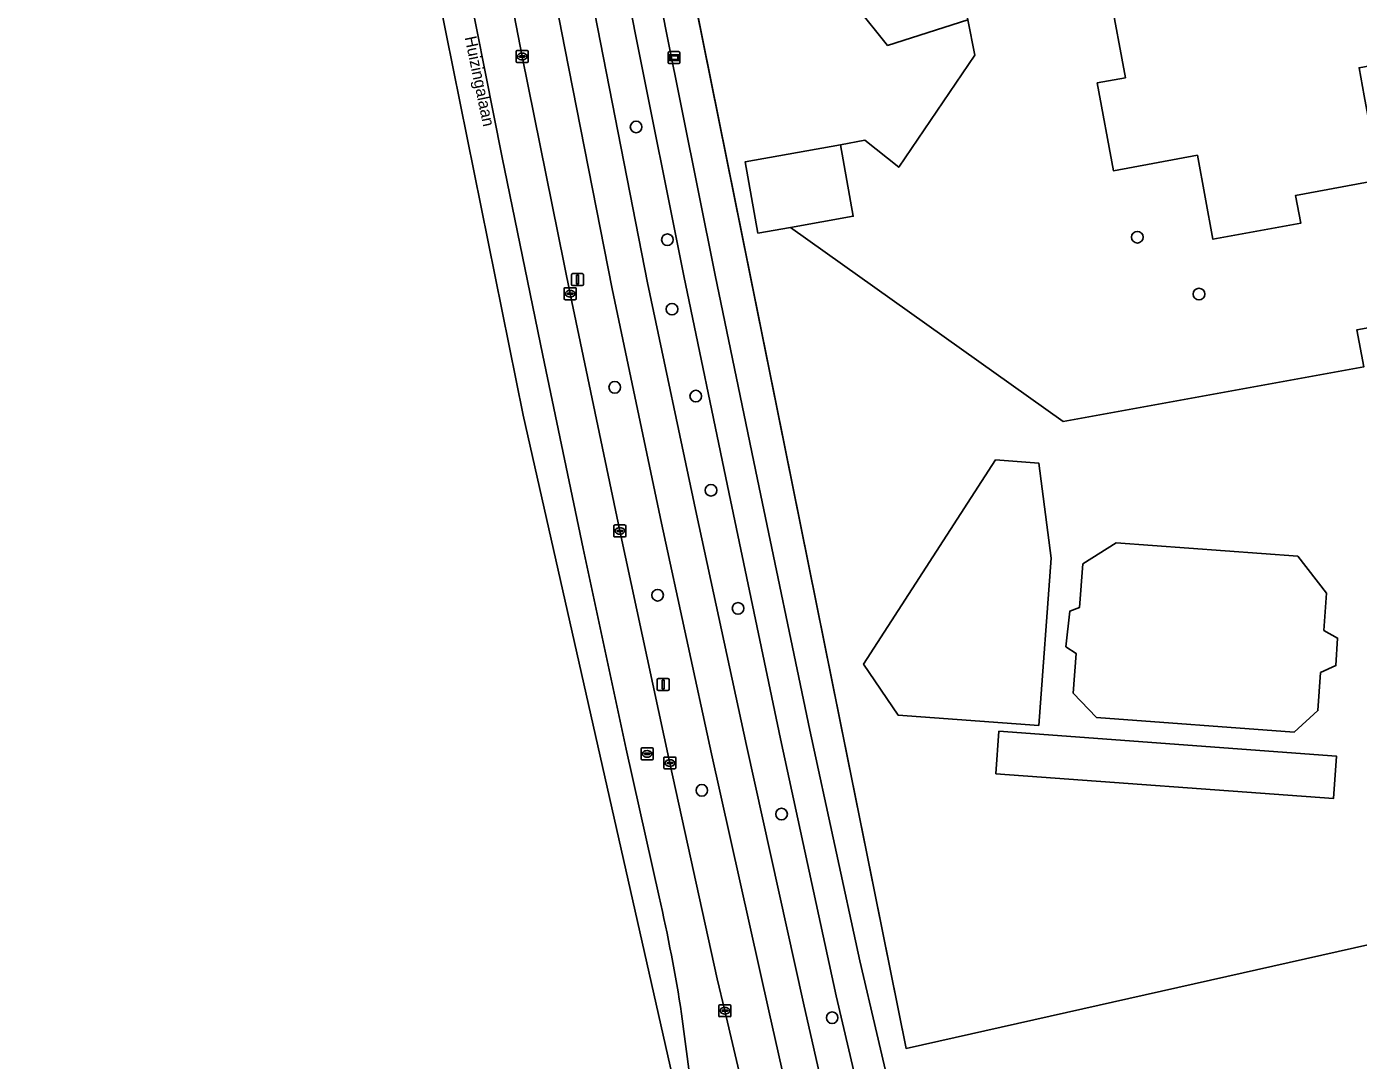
# Model space of a CAD drawing. Extents: x 159451 to 160664, y 388402 to 389723.
# Drawn here: x 159488.5 to 159600.6, y 388755.7 to 388842.8 of the extents above; entities that cross this region are included whole.
import ezdxf

# ---------------------------------------------------------------- set-up
doc = ezdxf.new("R2010")
doc.units = 0
for name, color, linetype in [('IMGEO_Berm_groen', 7, 'Continuous'), ('IMGEO_Boom', 7, 'Continuous'), ('IMGEO_Erf', 7, 'Continuous'), ('IMGEO_Fietspad_gesloten', 7, 'Continuous'), ('IMGEO_Groenvoorziening', 7, 'Continuous'), ('IMGEO_Hek', 7, 'Continuous'), ('IMGEO_Kolk', 7, 'Continuous'), ('IMGEO_Lichtmast', 7, 'Continuous'), ('IMGEO_Loofbos', 7, 'Continuous'), ('IMGEO_Openbare_ruimte_label', 7, 'Continuous'), ('IMGEO_OVBaan_gesloten', 7, 'Continuous'), ('IMGEO_Pand', 7, 'Continuous'), ('IMGEO_Rijbaan_regionaal_gesloten', 7, 'Continuous'), ('IMGEO_Rioolput', 7, 'Continuous'), ('IMGEO_Terreindeel_zand', 7, 'Continuous'), ('IMGEO_Verklikker', 7, 'Continuous'), ('IMGEO_Voetpad_open', 7, 'Continuous')]:
    doc.layers.add(name, color=color, linetype=linetype)

msp = doc.modelspace()

# ---------------------------------------------------------------- linework, layer by layer
at = {"layer": 'IMGEO_Berm_groen'}
for points in [[(159507.46, 388965.11), (159508.35, 388959.87), (159508.7, 388957.75), (159512.08, 388938.65), (159515.61, 388918.53), (159519.19, 388898.44), (159522.9, 388878.37), (159526.53, 388859.3), (159530.22, 388840.26), (159534.26, 388820.29), (159538.44, 388800.32), (159542.65, 388780.78), (159546.64, 388762.61), (159547.28, 388759.93), (159551.72, 388741.02), (159556.37, 388721.14), (159560.62, 388703.15), (159561.07, 388701.2), (159561.59, 388698.98)], [(159564.81, 388699.67), (159563.77, 388704.28), (159559.07, 388724.6), (159555.06, 388741.81), (159550.97, 388759.91), (159546.15, 388781.55), (159541.95, 388800.98), (159537.8, 388820.69), (159533.81, 388840.97), (159530.09, 388859.95), (159526.35, 388879.41), (159522.62, 388899.25), (159519.02, 388919.06), (159516.59, 388932.87), (159512.11, 388958.35), (159511.9, 388959.73), (159511.08, 388964.83)], [(159533.29, 388859.39), (159536.81, 388841.45), (159540.76, 388821.22), (159544.88, 388801.72), (159549.09, 388782.26), (159553.91, 388760.57), (159558.53, 388740.16), (159562.68, 388722.31), (159566.81, 388704.48), (159567.82, 388699.99), (159570.89, 388700.66), (159570.66, 388701.6), (159569.8, 388705.34), (159560.7, 388743.94), (159556.66, 388761.18), (159551.96, 388782.81), (159547.49, 388804.12), (159543.82, 388821.79), (159539.76, 388842.11), (159535.83, 388862.33)]]:
    msp.add_lwpolyline(points, dxfattribs=at)
at = {"layer": 'IMGEO_Boom'}
for centre in [(159539.81, 388834.33), (159542.44, 388824.84), (159582, 388825.05), (159587.19, 388820.26), (159542.83, 388818.99), (159538.01, 388812.41), (159544.83, 388811.67), (159546.11, 388803.74), (159541.62, 388794.91), (159548.39, 388793.8), (159545.34, 388778.48), (159552.05, 388776.48), (159556.31, 388759.34)]:
    msp.add_circle(centre, 0.489, dxfattribs=at)
at = {"layer": 'IMGEO_Erf'}
for points in [[(159538.55, 388875.67), (159562.53, 388756.76), (159678.25, 388782.74), (159689.42, 388833.24), (159688.56, 388837.48), (159685.61, 388852.04)], [(159662.98, 388848.82), (159665.86, 388835.05), (159663.92, 388832.1), (159657.18, 388821.94), (159652.89, 388824.78), (159637.51, 388830.55), (159632.91, 388823.15), (159600.49, 388817.26), (159601.06, 388814.13), (159575.75, 388809.53), (159552.81, 388825.88), (159550.06, 388825.39), (159548.99, 388831.4), (159557.02, 388832.83), (159559.07, 388833.23), (159561.91, 388830.94), (159568.33, 388840.38), (159567.72, 388843.34), (159560.98, 388841.19), (159555.74, 388847.74)]]:
    msp.add_lwpolyline(points, dxfattribs=at)
for points in [[(159574.74, 388798.04), (159573.7, 388783.95), (159561.86, 388784.82), (159558.95, 388789.11), (159570.07, 388806.3), (159573.7, 388806.03)], [(159597.7, 388791.94), (159597.93, 388795.08), (159595.51, 388798.19), (159580.22, 388799.32), (159577.4, 388797.55), (159577.13, 388793.87), (159576.32, 388793.57), (159575.99, 388790.57), (159576.84, 388790.01), (159576.6, 388786.67), (159578.57, 388784.61), (159595.21, 388783.38), (159597.2, 388785.2), (159597.43, 388788.39), (159598.71, 388788.98), (159598.86, 388791.3)], [(159597.7, 388791.94), (159598.86, 388791.3), (159598.71, 388788.98), (159597.43, 388788.39), (159597.2, 388785.2), (159595.21, 388783.38), (159578.57, 388784.61), (159576.6, 388786.67), (159576.84, 388790.01), (159575.99, 388790.57), (159576.32, 388793.57), (159577.13, 388793.87), (159577.4, 388797.55), (159580.22, 388799.32), (159595.51, 388798.19), (159597.93, 388795.08)], [(159570.35, 388783.45), (159570.09, 388779.88), (159598.51, 388777.78), (159598.77, 388781.35)], [(159598.77, 388781.35), (159598.51, 388777.78), (159570.09, 388779.88), (159570.35, 388783.45)]]:
    msp.add_lwpolyline(points, close=True, dxfattribs=at)
at = {"layer": 'IMGEO_Fietspad_gesloten'}
for points in [[(159540.76, 388821.22), (159536.81, 388841.45), (159533.29, 388859.39), (159529.26, 388880.34), (159525.53, 388900.16), (159521.97, 388919.7), (159518.43, 388939.84), (159516.78, 388949.35), (159515.14, 388958.74), (159514.42, 388963.29)], [(159530.09, 388859.95), (159533.81, 388840.97), (159537.8, 388820.69), (159541.95, 388800.98), (159546.15, 388781.55), (159550.97, 388759.91), (159555.06, 388741.81), (159559.07, 388724.6), (159563.77, 388704.28), (159564.81, 388699.67), (159567.82, 388699.99), (159566.81, 388704.48), (159562.68, 388722.31), (159558.53, 388740.16), (159553.91, 388760.57), (159549.09, 388782.26), (159544.88, 388801.72), (159540.76, 388821.22)]]:
    msp.add_lwpolyline(points, dxfattribs=at)
at = {"layer": 'IMGEO_Groenvoorziening'}
msp.add_lwpolyline([(159574.74, 388798.04), (159573.7, 388806.03), (159570.07, 388806.3), (159558.95, 388789.11), (159561.86, 388784.82), (159573.7, 388783.95)], close=True, dxfattribs=at)
at = {"layer": 'IMGEO_Hek'}
msp.add_lwpolyline([(159678.25, 388782.74), (159562.53, 388756.76), (159538.54, 388875.75), (159538.12, 388877.8), (159532.82, 388904.1), (159527.33, 388934.89), (159516.65, 389000), (159504.91, 389075.55), (159505.31, 389078.14), (159506.99, 389079.73), (159534.92, 389087.14), (159543.41, 389088.84), (159556.65, 389090.59), (159574.7, 389093.29)], dxfattribs=at)
at = {"layer": 'IMGEO_Kolk'}
for p, q in [((159529.72, 388839.84), (159529.72, 388840.69)), ((159529.79, 388840.76), (159530.64, 388840.76)), ((159530.72, 388840.69), (159530.72, 388839.84)), ((159530.64, 388839.76), (159529.79, 388839.76)), ((159529.98, 388840.26), (159529.98, 388840.27)), ((159530.02, 388840.31), (159530.42, 388840.31)), ((159530.41, 388840.22), (159530.02, 388840.22)), ((159530.23, 388839.98), (159530.2, 388839.98)), ((159530.21, 388840.54), (159530.23, 388840.54)), ((159530.46, 388840.27), (159530.46, 388840.26)), ((159533.76, 388819.87), (159533.76, 388820.72)), ((159533.83, 388820.79), (159534.69, 388820.79)), ((159534.25, 388820.57), (159534.27, 388820.57)), ((159534.76, 388820.72), (159534.76, 388819.87)), ((159534.69, 388819.79), (159533.83, 388819.79)), ((159534.02, 388820.29), (159534.02, 388820.3)), ((159534.06, 388820.34), (159534.46, 388820.34)), ((159534.45, 388820.25), (159534.06, 388820.25)), ((159534.27, 388820.01), (159534.24, 388820.01)), ((159534.5, 388820.3), (159534.5, 388820.29)), ((159537.94, 388799.89), (159537.94, 388800.75)), ((159538.01, 388800.82), (159538.87, 388800.82)), ((159538.2, 388800.31), (159538.2, 388800.33)), ((159538.24, 388800.36), (159538.64, 388800.36)), ((159538.43, 388800.6), (159538.45, 388800.6)), ((159538.68, 388800.33), (159538.68, 388800.31)), ((159538.94, 388800.75), (159538.94, 388799.89)), ((159538.87, 388799.82), (159538.01, 388799.82)), ((159538.64, 388800.28), (159538.24, 388800.28)), ((159538.45, 388800.04), (159538.42, 388800.04)), ((159542.23, 388781.28), (159543.08, 388781.28)), ((159542.15, 388780.35), (159542.15, 388781.21)), ((159543.08, 388780.28), (159542.23, 388780.28)), ((159542.41, 388780.77), (159542.41, 388780.79)), ((159542.85, 388780.74), (159542.45, 388780.74)), ((159542.46, 388780.82), (159542.85, 388780.82)), ((159542.64, 388781.06), (159542.67, 388781.06)), ((159542.66, 388780.5), (159542.64, 388780.5)), ((159542.9, 388780.79), (159542.9, 388780.77)), ((159543.16, 388781.21), (159543.16, 388780.35)), ((159546.78, 388759.5), (159546.78, 388760.35)), ((159546.85, 388760.43), (159547.71, 388760.43)), ((159547.08, 388759.97), (159547.48, 388759.97)), ((159547.27, 388760.21), (159547.29, 388760.21)), ((159547.78, 388760.35), (159547.78, 388759.5)), ((159547.71, 388759.43), (159546.85, 388759.43)), ((159547.04, 388759.92), (159547.04, 388759.93)), ((159547.47, 388759.88), (159547.08, 388759.88)), ((159547.29, 388759.65), (159547.26, 388759.65)), ((159547.52, 388759.93), (159547.52, 388759.92))]:
    msp.add_line(p, q, dxfattribs=at)
for points in [[(159529.72, 388839.84), (159529.72, 388840.69)], [(159529.79, 388840.76), (159530.64, 388840.76)], [(159530.72, 388840.69), (159530.72, 388839.84)], [(159530.64, 388839.76), (159529.79, 388839.76)], [(159533.76, 388819.87), (159533.76, 388820.72)], [(159533.83, 388820.79), (159534.69, 388820.79)], [(159534.76, 388820.72), (159534.76, 388819.87)], [(159534.69, 388819.79), (159533.83, 388819.79)], [(159537.94, 388799.89), (159537.94, 388800.75)], [(159538.01, 388800.82), (159538.87, 388800.82)], [(159538.94, 388800.75), (159538.94, 388799.89)], [(159538.87, 388799.82), (159538.01, 388799.82)], [(159542.23, 388781.28), (159543.08, 388781.28)], [(159542.15, 388780.35), (159542.15, 388781.21)], [(159543.08, 388780.28), (159542.23, 388780.28)], [(159543.16, 388781.21), (159543.16, 388780.35)], [(159546.78, 388759.5), (159546.78, 388760.35)], [(159546.85, 388760.43), (159547.71, 388760.43)], [(159547.78, 388760.35), (159547.78, 388759.5)], [(159547.71, 388759.43), (159546.85, 388759.43)]]:
    msp.add_lwpolyline(points, dxfattribs=at)
for centre, radius, start, end in [((159529.79, 388840.69), 0.0765, 91.552, 178.448), ((159529.79, 388840.69), 0.0765, 91.552, 178.448), ((159530.64, 388840.69), 0.0765, 1.552, 88.448), ((159530.64, 388840.69), 0.0765, 1.552, 88.448), ((159529.79, 388839.84), 0.0765, 181.552, 268.448), ((159529.79, 388839.84), 0.0765, 181.552, 268.448), ((159530.02, 388840.27), 0.0403, 85.8775, 175.7526), ((159530.01, 388840.26), 0.0366, 178.938, 274.7102), ((159530.42, 388840.26), 0.043, 264.8664, 352.4533), ((159530.42, 388840.27), 0.0386, 1.7309, 96.639), ((159530.64, 388839.84), 0.0765, 271.552, 358.448), ((159530.64, 388839.84), 0.0765, 271.552, 358.448), ((159533.83, 388820.72), 0.0765, 91.552, 178.448), ((159533.83, 388820.72), 0.0765, 91.552, 178.448), ((159534.68, 388820.72), 0.0765, 1.552, 88.448), ((159534.68, 388820.72), 0.0765, 1.552, 88.448), ((159533.83, 388819.87), 0.0765, 181.552, 268.448), ((159533.83, 388819.87), 0.0765, 181.552, 268.448), ((159534.06, 388820.3), 0.0403, 85.8775, 175.7526), ((159534.05, 388820.29), 0.0366, 178.938, 274.7102), ((159534.46, 388820.29), 0.043, 264.8664, 352.4533), ((159534.46, 388820.3), 0.0386, 1.7309, 96.639), ((159534.68, 388819.87), 0.0765, 271.552, 358.448), ((159534.68, 388819.87), 0.0765, 271.552, 358.448), ((159538.02, 388800.74), 0.0765, 91.552, 178.448), ((159538.02, 388800.74), 0.0765, 91.552, 178.448), ((159538.24, 388800.32), 0.0403, 85.8775, 175.7526), ((159538.64, 388800.32), 0.0386, 1.7309, 96.639), ((159538.86, 388800.74), 0.0765, 1.552, 88.448), ((159538.86, 388800.74), 0.0765, 1.552, 88.448), ((159538.02, 388799.89), 0.0765, 181.552, 268.448), ((159538.02, 388799.89), 0.0765, 181.552, 268.448), ((159538.23, 388800.31), 0.0366, 178.938, 274.7102), ((159538.64, 388800.32), 0.043, 264.8664, 352.4533), ((159538.86, 388799.89), 0.0765, 271.552, 358.448), ((159538.86, 388799.89), 0.0765, 271.552, 358.448), ((159542.23, 388781.21), 0.0765, 91.552, 178.448), ((159542.23, 388781.21), 0.0765, 91.552, 178.448), ((159543.08, 388781.21), 0.0765, 1.552, 88.448), ((159543.08, 388781.21), 0.0765, 1.552, 88.448), ((159542.23, 388780.36), 0.0765, 181.552, 268.448), ((159542.23, 388780.36), 0.0765, 181.552, 268.448), ((159542.45, 388780.78), 0.0403, 85.8775, 175.7526), ((159542.45, 388780.77), 0.0366, 178.938, 274.7102), ((159542.86, 388780.79), 0.0386, 1.7309, 96.639), ((159542.85, 388780.78), 0.043, 264.8664, 352.4533), ((159543.08, 388780.36), 0.0765, 271.552, 358.448), ((159543.08, 388780.36), 0.0765, 271.552, 358.448), ((159546.85, 388760.35), 0.0765, 91.552, 178.448), ((159546.85, 388760.35), 0.0765, 91.552, 178.448), ((159547.08, 388759.93), 0.0403, 85.8775, 175.7526), ((159547.48, 388759.93), 0.0386, 1.7309, 96.639), ((159547.7, 388760.35), 0.0765, 1.552, 88.448), ((159547.7, 388760.35), 0.0765, 1.552, 88.448), ((159546.85, 388759.5), 0.0765, 181.552, 268.448), ((159546.85, 388759.5), 0.0765, 181.552, 268.448), ((159547.07, 388759.92), 0.0366, 178.938, 274.7102), ((159547.48, 388759.93), 0.043, 264.8664, 352.4533), ((159547.7, 388759.5), 0.0765, 271.552, 358.448), ((159547.7, 388759.5), 0.0765, 271.552, 358.448)]:
    msp.add_arc(centre, radius, start, end, dxfattribs=at)
for centre, major_axis, ratio, start_param, end_param in [((159530.2, 388840.26), (-0.387, 0.002), 0.722429, 4.712389, 7.853982), ((159530.23, 388840.26), (-0.39, 0.002), 0.717154, 1.570796, 4.712389), ((159534.25, 388820.29), (-0.387, 0.002), 0.722429, 4.712389, 7.853982), ((159534.27, 388820.29), (-0.39, 0.002), 0.717154, 1.570796, 4.712389), ((159538.43, 388800.32), (-0.387, 0.002), 0.722429, 4.712389, 7.853982), ((159538.45, 388800.32), (-0.39, 0.002), 0.717154, 1.570796, 4.712389), ((159542.64, 388780.78), (-0.387, 0.002), 0.722429, 4.712389, 7.853982), ((159542.67, 388780.78), (-0.39, 0.002), 0.717154, 1.570796, 4.712389), ((159547.27, 388759.93), (-0.387, 0.002), 0.722429, 4.712389, 7.853982), ((159547.29, 388759.93), (-0.39, 0.002), 0.717154, 1.570796, 4.712389)]:
    msp.add_ellipse(centre, major_axis=major_axis, ratio=ratio, start_param=start_param, end_param=end_param, dxfattribs=at)
at = {"layer": 'IMGEO_Lichtmast'}
for p, q in [((159534.38, 388821.08), (159534.38, 388821.88)), ((159534.38, 388821.88), (159534.38, 388821.08)), ((159534.48, 388821.98), (159535.27, 388821.98)), ((159535.27, 388821.98), (159534.48, 388821.98)), ((159535.37, 388821.88), (159535.37, 388821.08)), ((159535.37, 388821.08), (159535.37, 388821.88)), ((159535.27, 388820.98), (159534.48, 388820.98)), ((159534.48, 388820.98), (159535.27, 388820.98)), ((159541.59, 388786.99), (159541.59, 388787.79)), ((159541.59, 388787.79), (159541.59, 388786.99)), ((159541.69, 388787.89), (159542.48, 388787.89)), ((159542.48, 388787.89), (159541.69, 388787.89)), ((159542.48, 388786.89), (159541.69, 388786.89)), ((159541.69, 388786.89), (159542.48, 388786.89)), ((159542.58, 388787.79), (159542.58, 388786.99)), ((159542.58, 388786.99), (159542.58, 388787.79))]:
    msp.add_line(p, q, dxfattribs=at)
for points in [[(159534.8, 388821.86), (159534.95, 388821.86), (159534.95, 388821.11), (159534.8, 388821.11), (159534.8, 388821.86)], [(159542.01, 388787.77), (159542.16, 388787.77), (159542.16, 388787.02), (159542.01, 388787.02), (159542.01, 388787.77)]]:
    msp.add_lwpolyline(points, dxfattribs=at)
for centre, start, end in [((159534.48, 388821.88), 90, 180), ((159534.48, 388821.88), 90, 180), ((159535.27, 388821.88), 0, 90), ((159535.27, 388821.88), 360, 90), ((159534.48, 388821.08), 180, 270), ((159534.48, 388821.08), 180, 270), ((159535.27, 388821.08), 270, 0), ((159535.27, 388821.08), 270, 0), ((159541.69, 388787.79), 90, 180), ((159541.69, 388787.79), 90, 180), ((159541.69, 388786.99), 180, 270), ((159541.69, 388786.99), 180, 270), ((159542.48, 388787.79), 0, 90), ((159542.48, 388787.79), 360, 90), ((159542.48, 388786.99), 270, 0), ((159542.48, 388786.99), 270, 0)]:
    msp.add_arc(centre, 0.1, start, end, dxfattribs=at)
at = {"layer": 'IMGEO_Loofbos'}
for points in [[(159538.55, 388875.67), (159536.01, 388875.2), (159538.42, 388862.69), (159542.32, 388842.53), (159546.47, 388821.86), (159550.03, 388804.64), (159554.44, 388783.56), (159558.65, 388764.13), (159562.92, 388745.78), (159569.25, 388718.9), (159573.34, 388701.53), (159573.64, 388700.25), (159573.96, 388700.31), (159663.02, 388721.57)], [(159666.77, 388725.32), (159672.12, 388750), (159679.19, 388782.55), (159690.15, 388833.04), (159689.11, 388837.98), (159686.23, 388851.74), (159685.61, 388852.04), (159688.56, 388837.48), (159689.42, 388833.24), (159678.25, 388782.74), (159562.53, 388756.76), (159538.55, 388875.67)]]:
    msp.add_lwpolyline(points, dxfattribs=at)
at = {"layer": 'IMGEO_OVBaan_gesloten'}
for points in [[(159492.58, 389017.29), (159489.48, 389025.16), (159488.5, 389027.73), (159489.8, 389018.46), (159497.36, 388989.59), (159522.05, 388850.95), (159530.3, 388810.06), (159544.83, 388745.7)], [(159541.75, 388769.52), (159538.98, 388781.96), (159535.34, 388798.85), (159531.95, 388815.1), (159528.54, 388831.76), (159524.96, 388849.75), (159521.55, 388867.6), (159517.66, 388888.54), (159514.58, 388905.28), (159510.84, 388926.49), (159507.6, 388945.01), (159503.76, 388967.73), (159500.27, 388989.26), (159500.03, 388990.58), (159499.23, 388994.84)], [(159544.31, 388754.59), (159543.64, 388759.66)]]:
    msp.add_lwpolyline(points, dxfattribs=at)
msp.add_arc((159393.65, 388735.92), 151.86, 8.996, 12.7816, dxfattribs=at)
at = {"layer": 'IMGEO_Pand'}
msp.add_lwpolyline([(159579.69, 388845.56), (159580.99, 388838.48), (159578.62, 388838.04), (159579.98, 388830.65), (159587.06, 388831.95), (159588.36, 388824.87), (159595.75, 388826.23), (159595.32, 388828.57), (159602.4, 388829.87), (159601.1, 388836.96), (159600.67, 388839.31), (159603.51, 388839.83), (159603.94, 388837.48), (159613.69, 388839.26), (159612.61, 388845.16)], dxfattribs=at)
msp.add_lwpolyline([(159557.02, 388832.83), (159548.99, 388831.4), (159550.06, 388825.39), (159552.81, 388825.88), (159558.09, 388826.82)], close=True, dxfattribs=at)
at = {"layer": 'IMGEO_Rijbaan_regionaal_gesloten'}
for points in [[(159499.23, 388994.84), (159500.03, 388990.58), (159500.27, 388989.26), (159503.76, 388967.73), (159507.6, 388945.01), (159510.84, 388926.49), (159514.58, 388905.28), (159517.66, 388888.54), (159521.55, 388867.6), (159524.96, 388849.75), (159528.54, 388831.76), (159531.95, 388815.1), (159535.34, 388798.85), (159538.98, 388781.96), (159541.75, 388769.52)], [(159563.34, 388663.49), (159569.16, 388664.89), (159567.8, 388671.02), (159564.46, 388686.08), (159563.1, 388692.2), (159562.4, 388695.61), (159561.98, 388697.35), (159561.59, 388698.98), (159561.07, 388701.2), (159560.62, 388703.15), (159556.37, 388721.14), (159551.72, 388741.02), (159547.28, 388759.93), (159546.64, 388762.61), (159542.65, 388780.78), (159538.44, 388800.32), (159534.26, 388820.29), (159530.22, 388840.26), (159526.53, 388859.3)], [(159543.64, 388759.66), (159544.31, 388754.59)]]:
    msp.add_lwpolyline(points, dxfattribs=at)
msp.add_arc((159393.65, 388735.92), 151.86, 8.996, 12.7816, dxfattribs=at)
at = {"layer": 'IMGEO_Rioolput'}
for p, q in [((159540.24, 388781.13), (159540.24, 388781.98)), ((159540.32, 388782.06), (159541.17, 388782.06)), ((159540.5, 388781.55), (159540.5, 388781.56)), ((159540.54, 388781.6), (159540.94, 388781.6)), ((159540.94, 388781.51), (159540.54, 388781.51)), ((159540.73, 388781.83), (159540.76, 388781.83)), ((159540.75, 388781.28), (159540.73, 388781.28)), ((159540.99, 388781.56), (159540.99, 388781.55)), ((159541.24, 388781.98), (159541.24, 388781.13)), ((159541.17, 388781.05), (159540.32, 388781.05))]:
    msp.add_line(p, q, dxfattribs=at)
for points in [[(159540.24, 388781.13), (159540.24, 388781.98)], [(159540.32, 388782.06), (159541.17, 388782.06)], [(159541.24, 388781.98), (159541.24, 388781.13)], [(159541.17, 388781.05), (159540.32, 388781.05)]]:
    msp.add_lwpolyline(points, dxfattribs=at)
for centre, radius, start, end in [((159540.32, 388781.98), 0.0765, 91.552, 178.448), ((159540.32, 388781.98), 0.0765, 91.552, 178.448), ((159540.54, 388781.56), 0.0403, 85.8775, 175.7526), ((159540.54, 388781.55), 0.0366, 178.938, 274.7102), ((159540.95, 388781.56), 0.0386, 1.7309, 96.639), ((159540.94, 388781.55), 0.043, 264.8664, 352.4533), ((159541.17, 388781.98), 0.0765, 1.552, 88.448), ((159541.17, 388781.98), 0.0765, 1.552, 88.448), ((159540.32, 388781.13), 0.0765, 181.552, 268.448), ((159540.32, 388781.13), 0.0765, 181.552, 268.448), ((159541.17, 388781.13), 0.0765, 271.552, 358.448), ((159541.17, 388781.13), 0.0765, 271.552, 358.448)]:
    msp.add_arc(centre, radius, start, end, dxfattribs=at)
for centre, major_axis, ratio, start_param, end_param in [((159540.73, 388781.55), (-0.387, 0.002), 0.722429, 4.712389, 7.853982), ((159540.75, 388781.55), (-0.39, 0.002), 0.717154, 1.570796, 4.712389)]:
    msp.add_ellipse(centre, major_axis=major_axis, ratio=ratio, start_param=start_param, end_param=end_param, dxfattribs=at)
at = {"layer": 'IMGEO_Terreindeel_zand'}
msp.add_lwpolyline([(159565.63, 388853.53), (159560.59, 388852.46), (159555.74, 388847.74), (159560.98, 388841.19), (159567.72, 388843.34)], close=True, dxfattribs=at)
at = {"layer": 'IMGEO_Verklikker'}
for p, q in [((159542.5, 388839.77), (159542.5, 388840.57)), ((159542.5, 388840.57), (159542.5, 388839.77)), ((159542.6, 388840.67), (159543.39, 388840.67)), ((159543.39, 388840.67), (159542.6, 388840.67)), ((159543.39, 388839.67), (159542.6, 388839.67)), ((159542.6, 388839.67), (159543.39, 388839.67)), ((159543.49, 388840.57), (159543.49, 388839.77)), ((159543.49, 388839.77), (159543.49, 388840.57))]:
    msp.add_line(p, q, dxfattribs=at)
for points in [[(159542.6, 388840.4), (159543.39, 388840.4), (159543.39, 388839.93), (159542.6, 388839.93), (159542.6, 388840.4)], [(159542.66, 388840.33), (159542.66, 388840), (159543.32, 388840), (159543.32, 388840.33), (159542.66, 388840.33)]]:
    msp.add_lwpolyline(points, dxfattribs=at)
for centre, start, end in [((159542.6, 388840.57), 90, 180), ((159542.6, 388840.57), 90, 180), ((159542.6, 388839.77), 180, 270), ((159542.6, 388839.77), 180, 270), ((159543.39, 388840.57), 0, 90), ((159543.39, 388840.57), 360, 90), ((159543.39, 388839.77), 270, 0), ((159543.39, 388839.77), 270, 0)]:
    msp.add_arc(centre, 0.1, start, end, dxfattribs=at)
at = {"layer": 'IMGEO_Voetpad_open'}
for points in [[(159535.83, 388862.33), (159539.76, 388842.11), (159543.82, 388821.79), (159547.49, 388804.12), (159551.96, 388782.81), (159556.66, 388761.18), (159560.7, 388743.94), (159569.8, 388705.34), (159570.66, 388701.6), (159570.89, 388700.66), (159573.34, 388701.53), (159569.25, 388718.9), (159562.92, 388745.78), (159558.65, 388764.13), (159554.44, 388783.56), (159550.03, 388804.64), (159546.47, 388821.86), (159542.32, 388842.53), (159538.42, 388862.69)], [(159567.72, 388843.34), (159568.33, 388840.38), (159561.91, 388830.94), (159559.07, 388833.23), (159557.02, 388832.83), (159558.09, 388826.82), (159552.81, 388825.88), (159575.75, 388809.53), (159601.06, 388814.13), (159600.49, 388817.26), (159632.91, 388823.15), (159637.51, 388830.55), (159652.89, 388824.78), (159659.63, 388834.94), (159663.92, 388832.1), (159665.86, 388835.05), (159662.98, 388848.82)], [(159612.61, 388845.16), (159613.69, 388839.26), (159603.94, 388837.48), (159603.51, 388839.83), (159600.67, 388839.31), (159601.1, 388836.96), (159602.4, 388829.87), (159595.32, 388828.57), (159595.75, 388826.23), (159588.36, 388824.87), (159587.06, 388831.95), (159579.98, 388830.65), (159578.62, 388838.04), (159580.99, 388838.48), (159579.69, 388845.56)]]:
    msp.add_lwpolyline(points, dxfattribs=at)

# ---------------------------------------------------------------- texts
at = {"layer": 'IMGEO_Openbare_ruimte_label'}
msp.add_text('Huizingalaan', height=1, rotation=281.7706, dxfattribs=at).set_placement((159525.37, 388841.87))

doc.saveas('drawing.dxf')
